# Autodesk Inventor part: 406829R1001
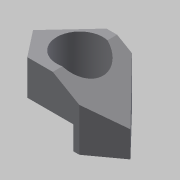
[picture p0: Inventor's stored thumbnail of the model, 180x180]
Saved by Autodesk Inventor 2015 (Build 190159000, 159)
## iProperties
Created: 2016-08
Part Number: 406829R1001
Material: 일반
Document SubType Name: Modeling
Designer: jio
Mass: 542.893 g
Surface Area: 683.408 cm^2
Volume: 542.893 cm^3
Density: 1 g/cm^3
Appearance: 기본값
Author: jio
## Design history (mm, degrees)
sketch "스케치1"
  geometry: L1 (-9.387, 55)-(34, 55); L2 (34, 55)-(104.673, -18.184); L3 (104.673, -18.184)-(54, -55); L4 (54, -55)-(-34.842, -55); L5 (-34.842, -55)-(-70, -10); L6 (-70, -10)-(-9.387, 55); C1 r 39.5 at (0, 0); 1 further point
  constraints: 12 end point, 1 centre point, 1 coincident, 1 horizontal, 1 parallel
  dimensions: "d8" = 79 diameter of C1; "d9" = 104 horizontal distance of L5.end L1.end; "d10" = 134 deg angle of L2 L1; "d11" = 144 deg angle of L4 L3; "d12" = 128 deg angle of L5 L4; "d13" = 99 deg angle of L5 L6; "d14" = 45 distance from line of L4 L5.end; "d15" = 110 distance between parallel lines of L1 L4; "d16" = 124 horizontal distance of L3.end L5.end; "d17" = 70 horizontal distance of L5.end point (0, 0); "d18" = 55 distance from line of point (0, 0) L4
extrude "돌출1" new body sketch "스케치1" distance "d19" = 100; taper "d20" = 0 deg
sketch "스케치2"
  geometry: L1 (-70, 15)-(44, 15); L2 (44, 15)-(44, -55); L3 (44, -55)-(-70, -55); L4 (-70, -55)-(-70, 15); L5 (-34.842, -55)-(54, -55) reference; 2 further points
  constraints: 8 end point, 2 parallel, 1 collinear, 1 horizontal, 1 perpendicular, 1 point on line
  dimensions: "d21" = 114 distance of L2.end L3.end; "d22" = 70 distance of L1.end L2.end
extrude "돌출2" cut sketch "스케치2" distance "d23" = 40; taper "d24" = 0 deg
sketch "스케치3"
  geometry: L1 (0, 0)-(88.842, 0) reference; L2 (43.515, 0)-(139.515, 0); L3 (139.515, 0)-(139.515, -55.426); L4 (139.515, -55.426)-(43.515, 0); L5 (139.515, -100)-(139.515, 0) reference; 1 further point
  constraints: 6 end point, 2 collinear, 1 horizontal, 1 perpendicular
  dimensions: "d25" = 96 distance of L2.start L2.end; "d26" = 30 deg angle of L1 L4
extrude "돌출3" cut sketch "스케치3" stored distance "d27" = 40; taper "d28" = 0 deg
node "솔리드1"
